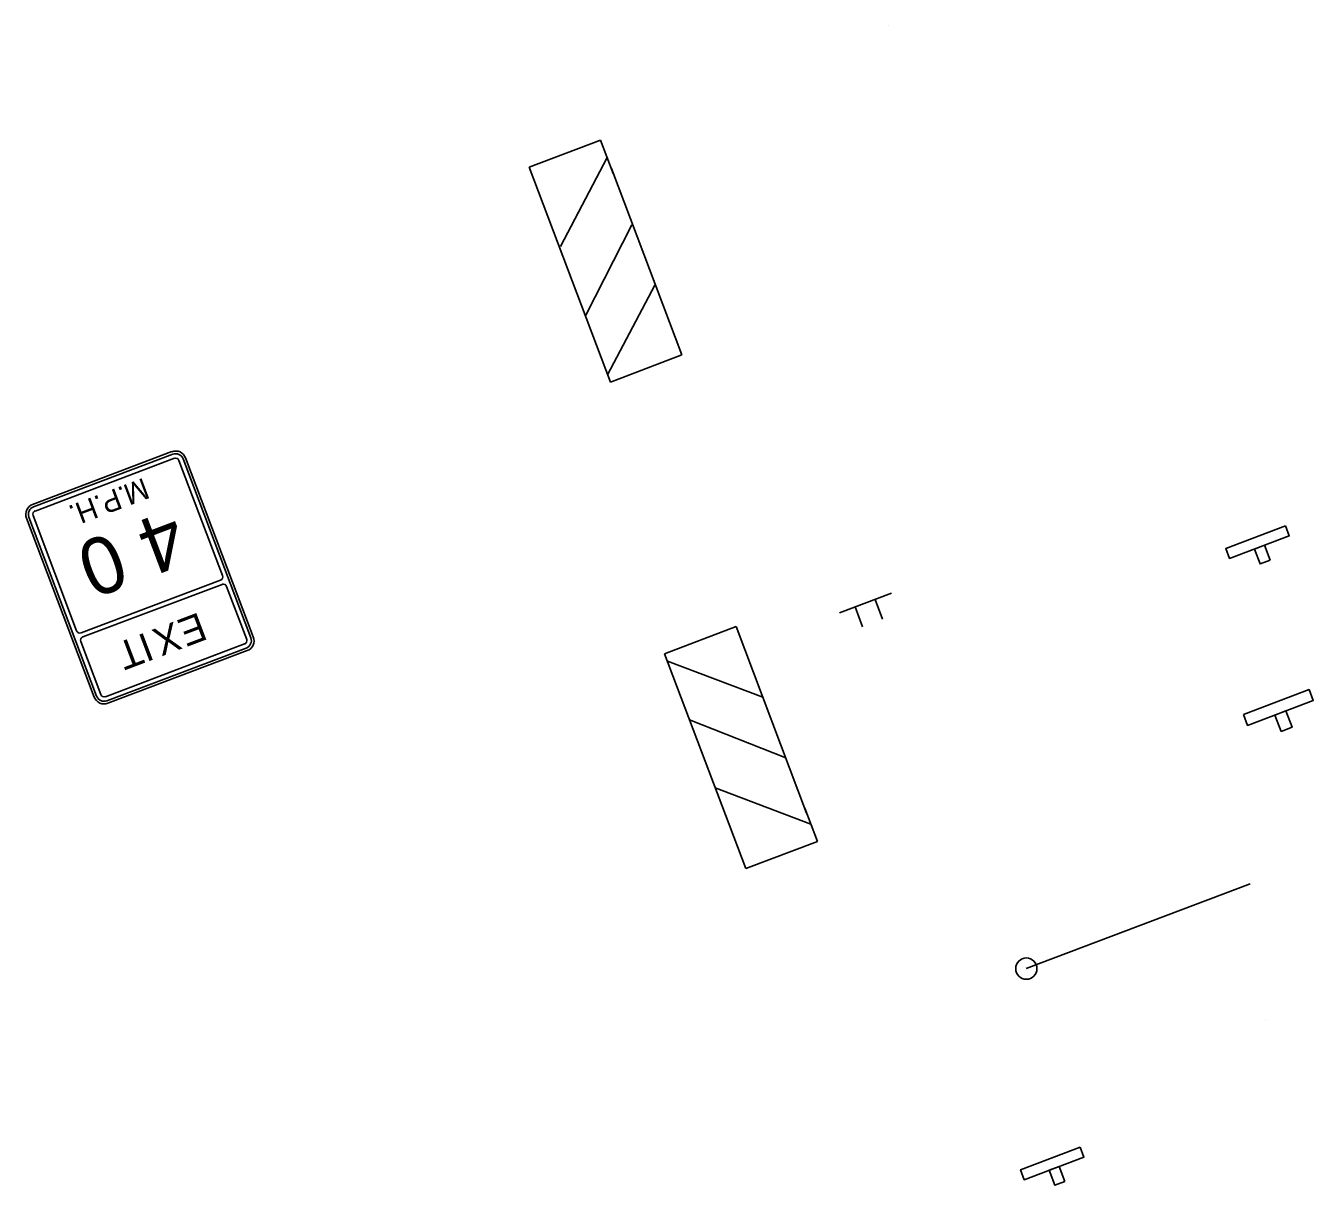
# Model space of a CAD drawing. Extents: x 1581789 to 1622364, y 1043167 to 1103486.
# Drawn here: x 1611554.3 to 1611796.4, y 1091956.6 to 1092174.7 of the extents above; entities that cross this region are included whole.
import ezdxf

# ---------------------------------------------------------------- set-up
doc = ezdxf.new("R2010")
doc.units = 0
for name, color, linetype in [('Level 15', 7, 'Continuous'), ('new 1B', 7, 'Continuous'), ('RD_PD_ALT1_TX', 7, 'Continuous')]:
    doc.layers.add(name, color=color, linetype=linetype)

msp = doc.modelspace()

# ---------------------------------------------------------------- linework, layer by layer
at = {"layer": 'Level 15'}
msp.add_line((1611742.49, 1091997.34), (1611784.58, 1092013.26), dxfattribs=at)
msp.add_circle((1611742.49, 1091997.34), 2, dxfattribs=at)
at = {"layer": 'new 1B'}
for p, q in [((1611716.64, 1092174.66), (1611716.64, 1092174.66)), ((1611662.44, 1092153.16), (1611648.97, 1092148.06)), ((1611664.81, 1092146.9), (1611662.44, 1092153.16)), ((1611663.68, 1092149.88), (1611654.86, 1092133.16)), ((1611648.97, 1092148.06), (1611664.26, 1092107.66)), ((1611677.72, 1092112.75), (1611664.47, 1092147.8)), ((1611668.29, 1092137.2), (1611659.64, 1092120.23)), ((1611672.6, 1092125.85), (1611663.74, 1092109.03)), ((1611664.26, 1092107.66), (1611677.72, 1092112.75)), ((1611674.46, 1092056.55), (1611687.93, 1092061.65)), ((1611687.93, 1092061.65), (1611701.18, 1092026.6)), ((1611689.74, 1092016.15), (1611674.46, 1092056.55)), ((1611692.95, 1092048.36), (1611674.98, 1092055.18)), ((1611697.25, 1092036.99), (1611679.16, 1092044.14)), ((1611701.97, 1092024.52), (1611683.99, 1092031.33)), ((1611700.84, 1092027.5), (1611703.21, 1092021.24)), ((1611703.21, 1092021.24), (1611689.74, 1092016.15)), ((1611787.39, 1091987.59), (1611787.39, 1091987.59))]:
    msp.add_line(p, q, dxfattribs=at)
for points in [[(1611791.24, 1092080.6), (1611780.01, 1092076.35), (1611780.72, 1092074.48), (1611791.94, 1092078.73)], [(1611788.33, 1092074.15), (1611786.46, 1092073.45), (1611785.4, 1092076.25), (1611787.27, 1092076.96)], [(1611783.32, 1092045.14), (1611795.67, 1092049.81), (1611796.45, 1092047.75), (1611784.1, 1092043.08)], [(1611790.41, 1092041.94), (1611792.47, 1092042.72), (1611791.31, 1092045.8), (1611789.25, 1092045.03)], [(1611752.63, 1091963.75), (1611741.4, 1091959.51), (1611742.11, 1091957.64), (1611753.33, 1091961.88)], [(1611749.72, 1091957.31), (1611747.85, 1091956.6), (1611746.79, 1091959.41), (1611748.66, 1091960.11)]]:
    msp.add_lwpolyline(points, close=True, dxfattribs=at)
at = {"layer": 'RD_PD_ALT1_TX'}
for p, q in [((1611581.81, 1092094.56), (1611555.62, 1092084.65)), ((1611597.12, 1092059.72), (1611584.38, 1092093.39)), ((1611554.45, 1092082.07), (1611567.19, 1092048.4)), ((1611707.38, 1092064.24), (1611717.14, 1092067.93)), ((1611714.06, 1092066.77), (1611715.47, 1092063.04)), ((1611710.3, 1092065.35), (1611711.71, 1092061.62)), ((1611569.77, 1092047.24), (1611595.95, 1092057.14))]:
    msp.add_line(p, q, dxfattribs=at)
for points in [[(1611581.81, 1092094.56), (1611555.62, 1092084.65)], [(1611555.79, 1092084.18), (1611581.98, 1092094.09)], [(1611582.28, 1092093.31), (1611556.09, 1092083.4)], [(1611591.33, 1092071.25), (1611583.14, 1092092.92)], [(1611583.92, 1092093.21), (1611596.65, 1092059.54)], [(1611597.12, 1092059.72), (1611584.38, 1092093.39)], [(1611554.45, 1092082.07), (1611567.19, 1092048.4)], [(1611567.65, 1092048.58), (1611554.92, 1092082.25)], [(1611555.7, 1092082.54), (1611563.89, 1092060.87)], [(1611564.75, 1092060.49), (1611590.94, 1092070.39)], [(1611591.24, 1092069.61), (1611565.05, 1092059.71)], [(1611595.87, 1092059.25), (1611592.1, 1092069.22)], [(1611564.66, 1092058.85), (1611568.43, 1092048.87)], [(1611569.29, 1092048.48), (1611595.48, 1092058.39)], [(1611595.78, 1092057.61), (1611569.59, 1092047.7)], [(1611569.77, 1092047.24), (1611595.95, 1092057.14)]]:
    msp.add_lwpolyline(points, dxfattribs=at)
for centre, radius, start, end in [((1611582.51, 1092092.68), 2, 20.7165, 110.7167), ((1611582.51, 1092092.68), 2, 20.7165, 110.7167), ((1611582.51, 1092092.68), 1.5, 20.7165, 110.7167), ((1611582.51, 1092092.68), 0.667, 20.7165, 110.7167), ((1611556.32, 1092082.78), 2, 110.7167, 200.7169), ((1611556.32, 1092082.78), 2, 110.7167, 200.7169), ((1611556.32, 1092082.78), 1.5, 110.7167, 200.7169), ((1611556.32, 1092082.78), 0.667, 110.7167, 200.7169), ((1611590.71, 1092071.02), 0.667, 290.7169, 20.7165), ((1611591.47, 1092068.99), 0.667, 20.7165, 110.7167), ((1611564.52, 1092061.11), 0.667, 200.7167, 290.7169), ((1611565.28, 1092059.08), 0.667, 110.7167, 200.7169), ((1611595.25, 1092059.01), 0.667, 290.7169, 20.7165), ((1611595.25, 1092059.01), 1.5, 290.7169, 20.7165), ((1611595.25, 1092059.01), 2, 290.7169, 20.7165), ((1611595.25, 1092059.01), 2, 290.7169, 20.7165), ((1611569.06, 1092049.11), 2, 200.7167, 290.7169), ((1611569.06, 1092049.11), 2, 200.7167, 290.7169), ((1611569.06, 1092049.11), 1.5, 200.7167, 290.7169), ((1611569.06, 1092049.11), 0.667, 200.7167, 290.7169)]:
    msp.add_arc(centre, radius, start, end, dxfattribs=at)

# ---------------------------------------------------------------- texts
for s, height, p in [('.', 4, (1611572.68, 1092088.25)), ('M', 4, (1611576.52, 1092089.71)), ('H', 4, (1611566.89, 1092086.06)), ('.', 4, (1611568.2, 1092086.56)), ('P', 4, (1611571.38, 1092087.76)), ('.', 4, (1611563.43, 1092084.75)), ('4', 10.67, (1611581.85, 1092083.88)), ('0', 10.67, (1611570.6, 1092079.62)), ('E', 5.33, (1611586.94, 1092064.42)), ('X', 5.33, (1611582.25, 1092062.65)), ('T', 5.33, (1611575.05, 1092059.93)), ('I', 5.33, (1611576.94, 1092060.64))]:
    msp.add_text(s, height=height, rotation=200.7167, dxfattribs=at).set_placement(p)

doc.saveas('drawing.dxf')
